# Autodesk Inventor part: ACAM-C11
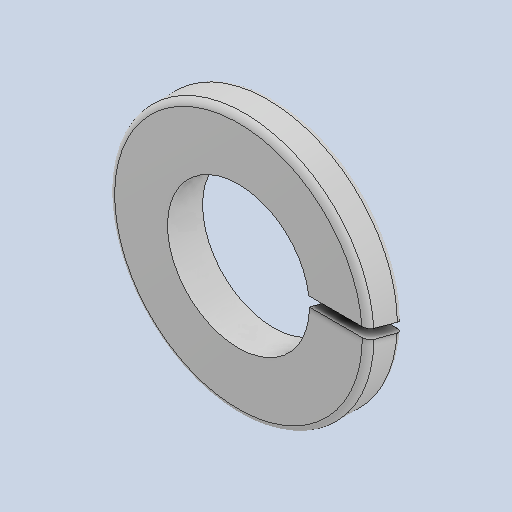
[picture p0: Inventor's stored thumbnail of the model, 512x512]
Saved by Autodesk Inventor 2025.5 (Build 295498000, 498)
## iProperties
Created: 2026-10
Part Number: ACAM-C11
Material: Genérico
Document SubType Name: Modeling
Designer: Luis M
Density: 1 g/cm^3
Appearance: Valor por defecto
Description: Arandela de presión M8 — DIN 127 B
Sending System: SolidEdge
MC: COSTA-PC
OS: Windows NT
OS_RELEASE: 6.1
FRU: Unigraphics Solutions
SITE: Huntsville, AL
FORMAT: text
GUISE: transmit
KEY: D:\Videos_Canal\GrabCAD\Arruela de pressao DIN 127 B\Arruela de pressao DIN 127 B - M8
FILE: D:\Videos_Canal\GrabCAD\Arruela de pressao DIN 127 B\Arruela de pressao DIN 127 B - M8.x_t
DATE: ter, abr 05 16
Material_BOM: Por especificar
Proceso_BOM: Comercial
Author: Luis M
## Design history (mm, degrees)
feature "Base1"
node "Sólido1"
